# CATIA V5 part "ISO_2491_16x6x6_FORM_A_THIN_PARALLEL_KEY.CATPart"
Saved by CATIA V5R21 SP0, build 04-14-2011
Part number: ISO 2491 KEY 16x6x4 THIN PARALLEL FORM A
Publications: "Mating Face", "Axis"
Bounding box of the stored display mesh (mm): x 0 to 6, y -3 to 14.853, z -3 to 3
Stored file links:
  C:\Users\MIRCEA\Desktop\MOM\Mogan\model\ISO_2491_16x6x6_FORM_A_THIN_PARALLEL_KEY.CATPart
  C:\Program Files (x86)\Dassault Systemes\B21\intel_a\startup\components\MechanicalStandardParts\ISO_Standards\Design_Tables\ISO_2491_THIN_PARALLEL_KEY_FORM_A.txt
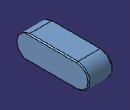
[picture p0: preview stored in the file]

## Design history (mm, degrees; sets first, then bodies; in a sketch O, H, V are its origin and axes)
Parameters
  l_length = 18 mm
  b_width = 6 mm
  h_thickness = 6 mm
  s_chamfer_min = 0.25 mm
  s_chamfer_max = 0.4 mm
  `Part Name` = "ISO 2491 KEY 14x6x4 THIN PARALLEL FORM A"
  `Part Number` = "ISO_2491_14x6x4_THIN_PARALLEL_KEY_FORM_A"
  PartName = "ISO_2491_16x6x4_FORM_A_THIN_PARALLEL_KEY"
  PartNumber = "ISO 2491 KEY 16x6x4 THIN PARALLEL FORM A"
Body1 "PartBody" (main body)
  Sketch1 on yz-plane, origin (0, 0, 0), H (0, 1, 0), V (0, 0, 1)
    line L1 (0, -3) -> (12, -3)
    arc A1 centre (12, 0) radius 3 from (12, -3) to (12, 3) ccw
    line L2 (12, 3) -> (0, 3)
    point P5 (0, 3)
    arc A2 centre (0, 0) radius 3 from (0, 3) to (0, -3) ccw
    point P6 (0, 0)
    radius A1 = 3 {= ( b_width * .5)}
    distance P5 H = 3 {= b_width /2}
    distance A2 A1 = 18 {= l_length}
    radius A2 = 3 {= ( b_width * .5)}
    tangency: A1 L1, L2 A1, A2 L2, L1 A2
    horizontal: L2 H
    coincidence: P6 V
  Pad1: profile Sketch1, direction (1, 0, 0), length 6 {= h_thickness}
  Chamfer1: length 0.25 {= s_chamfer_min}, angle 45, on edge [face of Pad1 | face of Pad1]
  Chamfer2: length 0.25 {= s_chamfer_min}, angle 45, on face of Pad1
